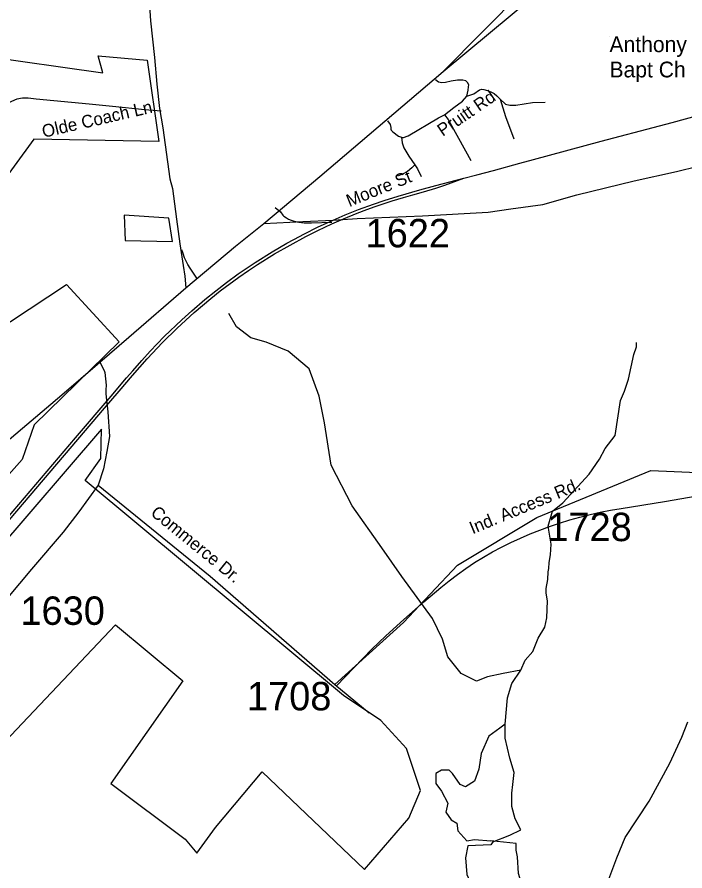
# Model space of a CAD drawing. Extents: x 1268485 to 1426702, y 514839 to 616766.
# Drawn here: x 1301450 to 1304922, y 604837 to 609275 of the extents above; entities that cross this region are included whole.
import ezdxf

# ---------------------------------------------------------------- set-up
doc = ezdxf.new("R2010")
doc.units = 0
for name, color, linetype in [('Old_Level_10', 7, 'Continuous'), ('Old_Level_11', 7, 'Continuous'), ('Old_Level_22', 7, 'Continuous'), ('Old_Level_29', 7, 'Continuous'), ('Old_Level_32', 7, 'Continuous'), ('Old_Level_35', 7, 'Continuous'), ('Old_Level_44', 7, 'Continuous'), ('Old_Level_48', 7, 'Continuous'), ('Old_Level_49', 7, 'Continuous'), ('Old_Level_59', 7, 'Continuous'), ('Old_Level_60', 7, 'Continuous'), ('Old_Level_62', 7, 'Continuous'), ('Old_Level_8', 7, 'Continuous')]:
    doc.layers.add(name, color=color, linetype=linetype)

msp = doc.modelspace()

# ---------------------------------------------------------------- linework, layer by layer
at = {"layer": 'Old_Level_22'}
msp.add_line((1304529.642, 609174.42), (1304529.642, 609174.42), dxfattribs=at)
at = {"layer": 'Old_Level_29'}
for points in [[(1307301.665, 612175.729), (1306990.814, 611915.748), (1305981.545, 611153.3), (1305301.834, 610576.313), (1304488.24, 609824.169), (1303665.665, 608991.958)], [(1303665.665, 608991.958), (1304147.082, 609394.076), (1304680.199, 609860.075), (1304851.89, 610014.029), (1305441.097, 610506.738), (1306242.545, 611187.726), (1307120.165, 611929.396), (1307298.407, 612079.072)], [(1302733.428, 608202.445), (1303023.601, 608446.138), (1303665.665, 608991.958)], [(1302328.086, 607867.766), (1302585.153, 608083.403), (1302733.428, 608202.445)], [(1301880.87, 607481.007), (1302031.63, 607610.661), (1302328.086, 607867.766)], [(1295913.804, 603932.683), (1296605.801, 604048.937), (1296902.372, 604101.251), (1297079.116, 604136.127), (1297222.907, 604162.284), (1297663.42, 604235.738), (1297967.327, 604313.416), (1298128.856, 604369.026), (1298187.507, 604397.7), (1298250.639, 604432.368), (1298337.291, 604483.438), (1298410.685, 604535.753), (1298756.683, 604817.667), (1299087.52, 605106.105), (1299361.806, 605336.452), (1299657.03, 605601.149), (1300038.825, 605917.718), (1300401.301, 606228.698), (1300998.717, 606732.393), (1301683.302, 607311.947), (1301880.87, 607481.007)]]:
    msp.add_lwpolyline(points, dxfattribs=at)
at = {"layer": 'Old_Level_32'}
msp.add_line((1303101.079, 605806.451), (1303280.855, 605658.92), dxfattribs=at)
for points in [[(1301699.924, 610705.926), (1301767.469, 610582.159), (1301834.533, 610454.543), (1302026.165, 610093.899), (1302056.034, 610013.493), (1302079.964, 609950.173), (1302099.437, 609815.028), (1302119.015, 609647.356), (1302126.398, 609518.581), (1302144.372, 609255.557), (1302163.844, 609063.738), (1302177.324, 608925.686), (1302191.213, 608799.361), (1302207.774, 608698.711), (1302244.977, 608434.03), (1302258.452, 608383.325), (1302278.331, 608224.396), (1302296.989, 608095.844), (1302313.574, 607983.878), (1302321.867, 607927.896), (1302328.086, 607867.766)], [(1302733.428, 608202.445), (1302935.923, 608212.993), (1303093.479, 608219.213), (1303217.867, 608227.507), (1303557.858, 608242.021), (1303898.565, 608261.077), (1304016.017, 608277.269), (1304183.694, 608300.564), (1304360.154, 608350.942), (1304658.683, 608423.51), (1304878.433, 608471.197), (1304990.382, 608500.225), (1305083.671, 608525.105)], [(1301880.87, 607481.007), (1301902.399, 607437.937), (1301905.453, 607428.011), (1301913.087, 607361.579), (1301911.56, 607337.908), (1301912.324, 607316.529), (1301915.641, 607284.17), (1301922.438, 607222.613), (1301930.073, 607094.713), (1301917.105, 607016.318), (1301899.131, 606926.222), (1301872.17, 606841.938)], [(1303101.079, 605806.451), (1303459.098, 606127.792), (1303740.033, 606425.882), (1304152.658, 606672.87), (1304744.812, 606917.984), (1305027.624, 606906.351), (1305172.752, 606903.559), (1305305.786, 606906.351), (1305384.861, 606908.212), (1305410.299, 606911.262)], [(1301872.17, 606841.938), (1301770.317, 606702.433), (1301689.435, 606597.805), (1301524.673, 606405.986), (1301335.946, 606182.197), (1301160.941, 605973.397), (1301055.973, 605852.751), (1300796.727, 605560.239), (1300682.892, 605470.142), (1300599.013, 605409.109), (1300363.645, 605262.608)], [(1301872.17, 606841.938), (1302453.006, 606368.168), (1303101.079, 605806.451)]]:
    msp.add_lwpolyline(points, dxfattribs=at)
at = {"layer": 'Old_Level_35'}
msp.add_line((1302791.953, 608285.263), (1302818.917, 608262.605), dxfattribs=at)
for points in [[(1303787.276, 608862.894), (1303795.785, 608894.832), (1303797.631, 608911.749), (1303798.246, 608923.334), (1303792.402, 608935.124), (1303782.97, 608942.814), (1303767.488, 608946.556), (1303739.293, 608947.478), (1303706.383, 608940.917), (1303677.163, 608935.33), (1303657.888, 608932.51), (1303641.484, 608937.123), (1303624.874, 608949.068)], [(1303787.276, 608862.894), (1303823.877, 608876.018), (1303854.533, 608896.267), (1303865.708, 608900.009), (1303876.576, 608899.086), (1303895.338, 608893.857), (1303913.28, 608886.373), (1303930.299, 608877.453), (1303943.833, 608866.124), (1303961.262, 608847.823)], [(1302198.84, 608786), (1302113.846, 608793.126), (1301945.703, 608810.299), (1301824.517, 608822.448), (1301548.825, 608848.49), (1301507.917, 608852.642), (1301478.389, 608853.36), (1301449.272, 608847.413), (1301421.59, 608836.187), (1301399.239, 608824.55), (1301380.477, 608808.197), (1301360.792, 608788.461), (1301342.235, 608768.827), (1301322.96, 608748.475), (1301296.508, 608721.614), (1301274.157, 608699.57), (1301250.576, 608685.729), (1301225.97, 608673.836), (1301206.08, 608668.557), (1301171.529, 608668.557), (1301130.416, 608676.451), (1300843.035, 608758.677)], [(1303672.241, 608767.084), (1303721.351, 608805.429), (1303765.643, 608838.391), (1303787.276, 608862.894)], [(1303961.262, 608847.823), (1303989.047, 608757.498), (1304032.108, 608641.541)], [(1303961.262, 608847.823), (1303989.97, 608822.192), (1304011.398, 608817.475), (1304042.258, 608816.963), (1304086.754, 608823.576), (1304130.123, 608830.138), (1304195.842, 608832.137)], [(1303448.325, 608651.23), (1303453.246, 608649.64), (1303459.602, 608649.64), (1303483.081, 608657.176), (1303641.381, 608751.398), (1303672.241, 608767.084)], [(1303672.241, 608767.084), (1303691.004, 608742.888), (1303744.01, 608645.078), (1303808.088, 608529.787)], [(1303375.531, 608735.147), (1303388.962, 608716.385), (1303393.166, 608700.698), (1303393.576, 608692.548), (1303395.114, 608687.062), (1303402.7, 608677.938), (1303432.536, 608656.51), (1303448.325, 608651.23)], [(1303448.325, 608651.23), (1303452.221, 608621.292), (1303461.345, 608594.994), (1303487.079, 608551.575), (1303517.53, 608506.771)], [(1303517.53, 608506.771), (1303502.253, 608491.392), (1303480.415, 608472.732), (1303457.654, 608460.326), (1303445.351, 608455.508), (1303426.999, 608447.459)], [(1303517.53, 608506.771), (1303531.371, 608486.419), (1303551.261, 608445.563)], [(1302818.917, 608262.605), (1302831.015, 608244.56), (1302836.552, 608239.126), (1302850.085, 608231.129), (1302861.671, 608224.875), (1302874.281, 608219.441), (1302885.662, 608215.443), (1302896.837, 608212.264), (1302914.164, 608208.933), (1302942.153, 608205.754), (1302981.113, 608204.524), (1303085.895, 608208.368)], [(1302384.207, 607918.322), (1302360.216, 607954.36), (1302350.271, 607970.303), (1302338.48, 607988.757), (1302330.996, 608002.548), (1302321.256, 608023.104), (1302312.746, 608046.634), (1302307.21, 608064.422)], [(1303109.989, 605797.93), (1303155.51, 605845.81), (1303293.51, 605989.449), (1303366.201, 606059.372), (1303460.73, 606144.366), (1303563.769, 606235.101), (1303653.479, 606310.663), (1303695.617, 606344.804), (1303738.781, 606377.561), (1303782.97, 606408.985), (1303828.081, 606439.025), (1303874.218, 606467.579), (1303921.277, 606494.697), (1303968.952, 606520.329), (1304017.652, 606544.371), (1304066.864, 606566.926), (1304116.897, 606587.944), (1304167.545, 606607.373), (1304218.705, 606626.648), (1304270.481, 606644.385), (1304322.769, 606660.687), (1304375.468, 606675.501), (1304428.576, 606688.83), (1304481.992, 606700.672), (1304535.716, 606710.975), (1304589.849, 606719.793), (1304815.612, 606757.625), (1305116.116, 606809.605)], [(1304526.283, 604794.559), (1304567.089, 604905.543), (1304611.893, 605009.607), (1304735.847, 605198.768), (1304843.089, 605397.617), (1304905.22, 605532.644), (1304936.798, 605610.768)]]:
    msp.add_lwpolyline(points, dxfattribs=at)
at = {"layer": 'Old_Level_44'}
for points in [[(1303772.204, 608437.873), (1303840.794, 608455.456), (1303926.096, 608477.756), (1304064.096, 608516.049), (1304134.531, 608535.119), (1304486.298, 608629.084), (1304789.263, 608709.772), (1304855.392, 608727.56), (1305063.007, 608783.899)], [(1301061.006, 606252.121), (1301904.59, 607241.548), (1301981.074, 607330.745), (1302049.869, 607411.793), (1302126.354, 607498.427), (1302206.427, 607584.087), (1302282.911, 607658.008), (1302371.494, 607739.056), (1302457.205, 607812.413), (1302506.623, 607851.168), (1302602.485, 607923.038), (1302652.415, 607957.692), (1302699.372, 607988.296), (1302787.544, 608043.866), (1302951.176, 608134.089), (1303012.999, 608165.667), (1303086.203, 608200.064), (1303146.385, 608226.31), (1303217.538, 608254.864), (1303267.879, 608274.242), (1303311.247, 608290.338), (1303399.112, 608319.148), (1303459.397, 608336.167), (1303507.482, 608351.239), (1303562.744, 608366.002), (1303627.54, 608385.38), (1303673.164, 608401.169), (1303772.204, 608437.873)], [(1302305.979, 607701.121), (1302357.755, 607748.386), (1302425.73, 607806.415), (1302482.632, 607852.5), (1302539.124, 607895.305), (1302599.922, 607940.212), (1302687.274, 607998.6), (1302776.881, 608054.323), (1302852.956, 608098.768), (1302887.917, 608117.94), (1302944.204, 608148.39), (1303011.461, 608182.019), (1303108.861, 608226.875), (1303155.203, 608246.508), (1303225.023, 608274.139), (1303303.045, 608301.769), (1303358.717, 608321.762), (1303431.1, 608344.574), (1303544.084, 608376.613), (1303627.027, 608399.836), (1303772.204, 608437.873)], [(1301399.547, 606671.708), (1301754.594, 607088.476), (1301938.526, 607303.525), (1302019.727, 607399.643), (1302051.715, 607436.45), (1302097.852, 607488.943), (1302142.655, 607538.925), (1302215.551, 607614.64), (1302305.979, 607701.121)]]:
    msp.add_lwpolyline(points, dxfattribs=at)
at = {"layer": 'Old_Level_48'}
for points in [[(1300082.431, 609203.831), (1300455.816, 609175.947), (1301247.169, 609125.755), (1301258.034, 609074.641), (1301896.015, 608985.307), (1301870.753, 609073.787), (1302125.665, 609051.172), (1302186.538, 608627.175), (1301537.852, 608640.173), (1301330.657, 608360.12), (1300943.328, 608529.667), (1300786.062, 608516.987), (1300422.853, 608638.662), (1300218.043, 608594.789), (1300004.201, 608601.272), (1300091.074, 608147.43), (1300371.743, 607972.377), (1300545.489, 607842.708), (1300832.84, 607615.787), (1301020.966, 607433.267)], [(1302006.971, 608244.297), (1302011.812, 608113.504), (1302258.735, 608108.66), (1302239.369, 608229.765), (1302006.971, 608244.297)], [(1301020.966, 607433.267), (1301706.458, 607885.096), (1301980.645, 607586.171), (1301539.27, 607155.629), (1301476.775, 606975.114), (1300871.597, 606296.924), (1300435.87, 605776.172), (1299988.039, 605364.414), (1299516.001, 604988.987), (1298826.099, 604637.782), (1298924.731, 604277.806), (1298791.586, 603042.532), (1298658.442, 602994.091), (1298196.563, 603806.755), (1297532.479, 603521.56), (1297216.508, 603426.705), (1296903.353, 603333.185), (1296988.082, 602751.88), (1296733.897, 602788.211), (1296746, 602412.785), (1296975.978, 601589.269)], [(1301888.295, 607132.551), (1300774.769, 605836.724), (1301295.221, 605412.856), (1301960.916, 606115.266), (1302311.919, 605824.614), (1301936.709, 605291.751), (1302324.022, 605001.098), (1302384.541, 604928.435), (1302481.369, 605061.65), (1302723.44, 605352.304), (1303255.996, 604843.661), (1303485.963, 605110.093), (1303546.481, 605255.419), (1303473.859, 605473.408), (1303340.721, 605618.735), (1303147.193, 605749.086), (1301803.571, 606866.119), (1301885.93, 606979.959), (1301888.295, 607132.551)]]:
    msp.add_lwpolyline(points, dxfattribs=at)
at = {"layer": 'Old_Level_49'}
for points in [[(1300082.431, 609203.831), (1300455.816, 609175.947), (1301247.169, 609125.755), (1301258.034, 609074.641), (1301896.015, 608985.307), (1301870.753, 609073.787), (1302125.665, 609051.172), (1302186.538, 608627.175), (1301537.852, 608640.173), (1301330.657, 608360.12), (1300943.328, 608529.667), (1300786.062, 608516.987), (1300422.853, 608638.662), (1300218.043, 608594.789), (1300004.201, 608601.272), (1300091.074, 608147.43), (1300371.743, 607972.377), (1300545.489, 607842.708), (1300832.84, 607615.787), (1301020.966, 607433.267)], [(1302006.971, 608244.297), (1302011.812, 608113.504), (1302258.735, 608108.66), (1302239.369, 608229.765), (1302006.971, 608244.297)], [(1301020.966, 607433.267), (1301706.458, 607885.096), (1301980.645, 607586.171), (1301539.27, 607155.629), (1301476.775, 606975.114), (1300871.597, 606296.924), (1300435.87, 605776.172), (1299988.039, 605364.414), (1299516.001, 604988.987), (1298826.099, 604637.782), (1298924.731, 604277.806), (1298791.586, 603042.532), (1298658.442, 602994.091), (1298196.563, 603806.755), (1297532.479, 603521.56), (1297216.508, 603426.705), (1296903.353, 603333.185), (1296988.082, 602751.88), (1296733.897, 602788.211), (1296746, 602412.785), (1296975.978, 601589.269)], [(1301888.295, 607132.551), (1300774.769, 605836.724), (1301295.221, 605412.856), (1301960.916, 606115.266), (1302311.919, 605824.614), (1301936.709, 605291.751), (1302324.022, 605001.098), (1302384.541, 604928.435), (1302481.369, 605061.65), (1302723.44, 605352.304), (1303255.996, 604843.661), (1303485.963, 605110.093), (1303546.481, 605255.419), (1303473.859, 605473.408), (1303340.721, 605618.735), (1303147.193, 605749.086), (1301803.571, 606866.119), (1301885.93, 606979.959), (1301888.295, 607132.551)]]:
    msp.add_lwpolyline(points, dxfattribs=at)
at = {"layer": 'Old_Level_59'}
for points in [[(1304068.101, 605880.031), (1303976.479, 605862.841), (1303896.309, 605845.652), (1303839.046, 605822.732), (1303758.876, 605862.841), (1303690.159, 605948.788), (1303661.527, 606040.465), (1303609.989, 606149.331), (1303449.65, 606367.065), (1303346.575, 606516.04), (1303191.962, 606733.772), (1303083.16, 606945.776), (1303048.802, 607166.374), (1303020.17, 607303.889), (1302968.632, 607447.135), (1302859.831, 607538.812), (1302745.303, 607584.65), (1302665.134, 607607.57), (1302590.69, 607664.868), (1302550.606, 607733.625)], [(1303987.931, 605599.269), (1303999.384, 605736.785), (1304022.29, 605811.272), (1304068.101, 605880.031), (1304091.007, 605931.599), (1304131.091, 605977.437), (1304159.723, 606046.195), (1304194.082, 606103.493), (1304204.677, 606152.183), (1304206.728, 606240.048), (1304199.653, 606280.238), (1304200.269, 606304.178), (1304209.393, 606351.955), (1304210.316, 606391.889), (1304214.622, 606407.78), (1304215.442, 606439.718), (1304222.312, 606479.549), (1304225.695, 606535.425), (1304211.546, 606629.391), (1304233.692, 606707.157), (1304286.698, 606749.807), (1304424.083, 606898.419), (1304478.012, 606977.057), (1304507.232, 607032.318), (1304558.802, 607099.011), (1304587.099, 607282.225), (1304608.22, 607329.695), (1304627.7, 607393.158), (1304656.715, 607520.393), (1304669.633, 607560.071), (1304670.145, 607584.011)]]:
    msp.add_lwpolyline(points, dxfattribs=at)
at = {"layer": 'Old_Level_60'}
for points in [[(1303987.931, 605599.269), (1303959.3, 605578.069), (1303902.036, 605537.961), (1303861.951, 605446.284), (1303850.498, 605366.067), (1303827.592, 605303.039), (1303781.781, 605274.39), (1303753.149, 605285.849), (1303713.065, 605343.147), (1303695.886, 605360.337), (1303655.8, 605360.337), (1303627.169, 605343.147), (1303627.169, 605291.579), (1303655.8, 605251.47), (1303690.159, 605188.442), (1303678.706, 605142.603), (1303707.338, 605102.495), (1303735.97, 605085.305), (1303741.697, 605045.197), (1303787.508, 604993.628), (1303827.592, 604999.358), (1303913.488, 604993.628)], [(1303923.533, 604987.82), (1304010.837, 605022.277), (1304068.101, 605050.926), (1304039.469, 605108.224), (1304022.29, 605171.252), (1304022.29, 605240.01), (1304028.017, 605285.849), (1304033.742, 605348.877), (1304010.837, 605423.365), (1303987.931, 605526.501), (1303987.931, 605599.269)], [(1303923.533, 604987.82), (1303913.488, 604973.002), (1303793.234, 604967.272), (1303781.781, 604904.243), (1303787.508, 604818.296), (1303821.866, 604743.808), (1303873.403, 604675.051), (1303884.857, 604623.483), (1303890.583, 604548.995), (1303924.941, 604468.778), (1303987.931, 604434.399), (1304056.648, 604417.209), (1304131.091, 604434.399), (1304194.082, 604508.886), (1304194.082, 604589.104), (1304165.45, 604652.132), (1304125.366, 604692.24), (1304073.828, 604766.728), (1304056.648, 604824.026), (1304050.922, 604909.973), (1304045.196, 604944.352), (1304045.196, 604978.731), (1303913.488, 604993.628)]]:
    msp.add_lwpolyline(points, dxfattribs=at)
at = {"layer": 'Old_Level_62'}
for points in [[(1304068.101, 605880.031), (1303976.479, 605862.841), (1303896.309, 605845.652), (1303839.046, 605822.732), (1303758.876, 605862.841), (1303690.159, 605948.788), (1303661.527, 606040.465), (1303609.989, 606149.331), (1303449.65, 606367.065), (1303346.575, 606516.04), (1303191.962, 606733.772), (1303083.16, 606945.776), (1303048.802, 607166.374), (1303020.17, 607303.889), (1302968.632, 607447.135), (1302859.831, 607538.812), (1302745.303, 607584.65), (1302665.134, 607607.57), (1302590.69, 607664.868), (1302550.606, 607733.625)], [(1303987.931, 605599.269), (1303999.384, 605736.785), (1304022.29, 605811.272), (1304068.101, 605880.031), (1304091.007, 605931.599), (1304131.091, 605977.437), (1304159.723, 606046.195), (1304194.082, 606103.493), (1304204.677, 606152.183), (1304206.728, 606240.048), (1304199.653, 606280.238), (1304200.269, 606304.178), (1304209.393, 606351.955), (1304210.316, 606391.889), (1304214.622, 606407.78), (1304215.442, 606439.718), (1304222.312, 606479.549), (1304225.695, 606535.425), (1304211.546, 606629.391), (1304233.692, 606707.157), (1304286.698, 606749.807), (1304424.083, 606898.419), (1304478.012, 606977.057), (1304507.232, 607032.318), (1304558.802, 607099.011), (1304587.099, 607282.225), (1304608.22, 607329.695), (1304627.7, 607393.158), (1304656.715, 607520.393), (1304669.633, 607560.071), (1304670.145, 607584.011)], [(1303987.931, 605599.269), (1303959.3, 605578.069), (1303902.036, 605537.961), (1303861.951, 605446.284), (1303850.498, 605366.067), (1303827.592, 605303.039), (1303781.781, 605274.39), (1303753.149, 605285.849), (1303713.065, 605343.147), (1303695.886, 605360.337), (1303655.8, 605360.337), (1303627.169, 605343.147), (1303627.169, 605291.579), (1303655.8, 605251.47), (1303690.159, 605188.442), (1303678.706, 605142.603), (1303707.338, 605102.495), (1303735.97, 605085.305), (1303741.697, 605045.197), (1303787.508, 604993.628), (1303827.592, 604999.358), (1303913.488, 604993.628)], [(1303923.533, 604987.82), (1304010.837, 605022.277), (1304068.101, 605050.926), (1304039.469, 605108.224), (1304022.29, 605171.252), (1304022.29, 605240.01), (1304028.017, 605285.849), (1304033.742, 605348.877), (1304010.837, 605423.365), (1303987.931, 605526.501), (1303987.931, 605599.269)], [(1303923.533, 604987.82), (1303913.488, 604973.002), (1303793.234, 604967.272), (1303781.781, 604904.243), (1303787.508, 604818.296), (1303821.866, 604743.808), (1303873.403, 604675.051), (1303884.857, 604623.483), (1303890.583, 604548.995), (1303924.941, 604468.778), (1303987.931, 604434.399), (1304056.648, 604417.209), (1304131.091, 604434.399), (1304194.082, 604508.886), (1304194.082, 604589.104), (1304165.45, 604652.132), (1304125.366, 604692.24), (1304073.828, 604766.728), (1304056.648, 604824.026), (1304050.922, 604909.973), (1304045.196, 604944.352), (1304045.196, 604978.731), (1303913.488, 604993.628)]]:
    msp.add_lwpolyline(points, dxfattribs=at)

# ---------------------------------------------------------------- texts
at = {"layer": 'Old_Level_10'}
for s, height, rotation, p in [('Pruitt Rd', 65.6167, 34.408975, (1303662.79, 608651.775)), ('Olde Coach Ln', 65.61666, 12.971667, (1301587.728, 608647.149)), ('Moore St', 65.6167, 22.045042, (1303177.384, 608286.632))]:
    msp.add_text(s, height=height, rotation=rotation, dxfattribs=at).set_placement(p)
at = {"layer": 'Old_Level_11'}
for s, rotation, p in [('Ind. Access Rd.', 22.486386, (1303818.013, 606585.957)), ('Commerce Dr.', 320.796928, (1302139.573, 606689.591))]:
    msp.add_text(s, height=65.61666, rotation=rotation, dxfattribs=at).set_placement(p)
at = {"layer": 'Old_Level_22'}
for s, height, p in [('Anthony Grove ', 82.02083, (1304529.642, 609092.399)), ('Bapt Ch', 82.0208, (1304529.642, 608961.166))]:
    msp.add_text(s, height=height, dxfattribs=at).set_placement(p)
at = {"layer": 'Old_Level_8'}
for s, p in [('1622', (1303261.552, 608077.901)), ('1728', (1304206.551, 606550.817)), ('1630', (1301467.23, 606115.658)), ('1708', (1302644.976, 605671.285))]:
    msp.add_text(s, height=147.6375, dxfattribs=at).set_placement(p)

doc.saveas('drawing.dxf')
